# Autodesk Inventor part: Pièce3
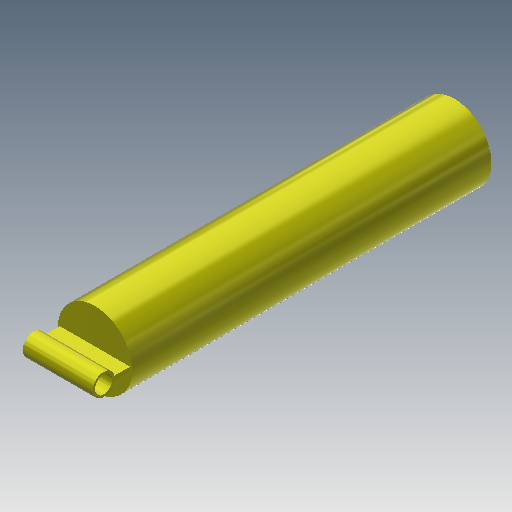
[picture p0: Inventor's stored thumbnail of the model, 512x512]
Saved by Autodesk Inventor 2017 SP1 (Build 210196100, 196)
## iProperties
Created: 2013-05
Part Number: Pièce3
Material: Générique
Document SubType Name: Modeling
Designer: jost thierry
Density: 1 g/cm^3
Mass: 4.62494 g
Surface Area: 94.8819 cm^2
Volume: 4.62494 cm^3
Appearance: Lisse - Jaune
Author: jost thierry
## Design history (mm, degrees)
sketch "Esquisse1"
  geometry: C1 r 7.5 at (0, 0); C2 r 8.5 at (0, 0); 1 further point
  constraints: 2 centre point, 1 coincident
  dimensions: "d0" = 15 diameter of C1; "d1" = 1 radial gap between concentric circles of C2 C1
extrude "Extrusion1" new body sketch "Esquisse1" distance "d2" = 43; taper "d4" = 0 deg; dims "d3" = 37, "d5" = 0
sketch "Esquisse2"
  geometry: C1 r 8.5 at (0, 0) reference; C2 r 8.5 at (0, 0)
  constraints: 1 centre point, 1 coincident, 1 concentric
extrude "Extrusion2" join sketch "Esquisse2" distance "d6" = 1; taper "d7" = 0 deg
sketch "Esquisse3"
  geometry: L1 (0, 0)-(-8.5, 0); C1 r 2.5 at (0, 0)
  constraints: 2 end point, 1 centre point, 1 coincident, 1 horizontal alignment, 1 other
  dimensions: "d8" = 5 diameter of C1
extrude "Extrusion3" join sketch "Esquisse3" distance "d9" = 1; taper "d10" = 0 deg
sketch "Esquisse4"
  geometry: L1 (-8, 0.5)-(8, 0.5); L2 (8, 0.5)-(8, -0.5); L3 (8, -0.5)-(-8, -0.5); L4 (-8, -0.5)-(-8, 0.5); C1 r 8.5 at (0, 0) reference
  constraints: 8 end point, 2 parallel, 1 horizontal, 1 perpendicular
  dimensions: "d11" = 1 distance of L1.end L2.end; "d12" = 16 distance of L1.start L1.end; "d13" = 0.5 vertical distance of C1.centre L3.end; "d14" = 8 horizontal distance of C1.centre L3.end
extrude "Extrusion4" join sketch "Esquisse4" distance "d15" = 6; taper "d16" = 0 deg
sketch "Esquisse5"
  geometry: L1 (-6, 1)-(-6, 0) reference; C1 r 2.5 at (-6, 0.5); 1 further point
  constraints: 1 centre point, 1 midpoint
  dimensions: "d17" = 5 diameter of C1
extrude "Extrusion5" join sketch "Esquisse5" stored distance "d18" = 10; taper "d19" = 0 deg
sketch "Esquisse6"
  geometry: C1 r 2 at (6, 0.5); A1 r 2.5 centre (6, 0.5) between (3.551, 0) and (3.551, 1) reference; 1 further point
  constraints: 1 centre point, 1 coincident
  dimensions: "d20" = 4 diameter of C1
extrude "Extrusion6" cut sketch "Esquisse6" stored distance "d21" = 10; taper "d22" = 0 deg
node "Solide1"
